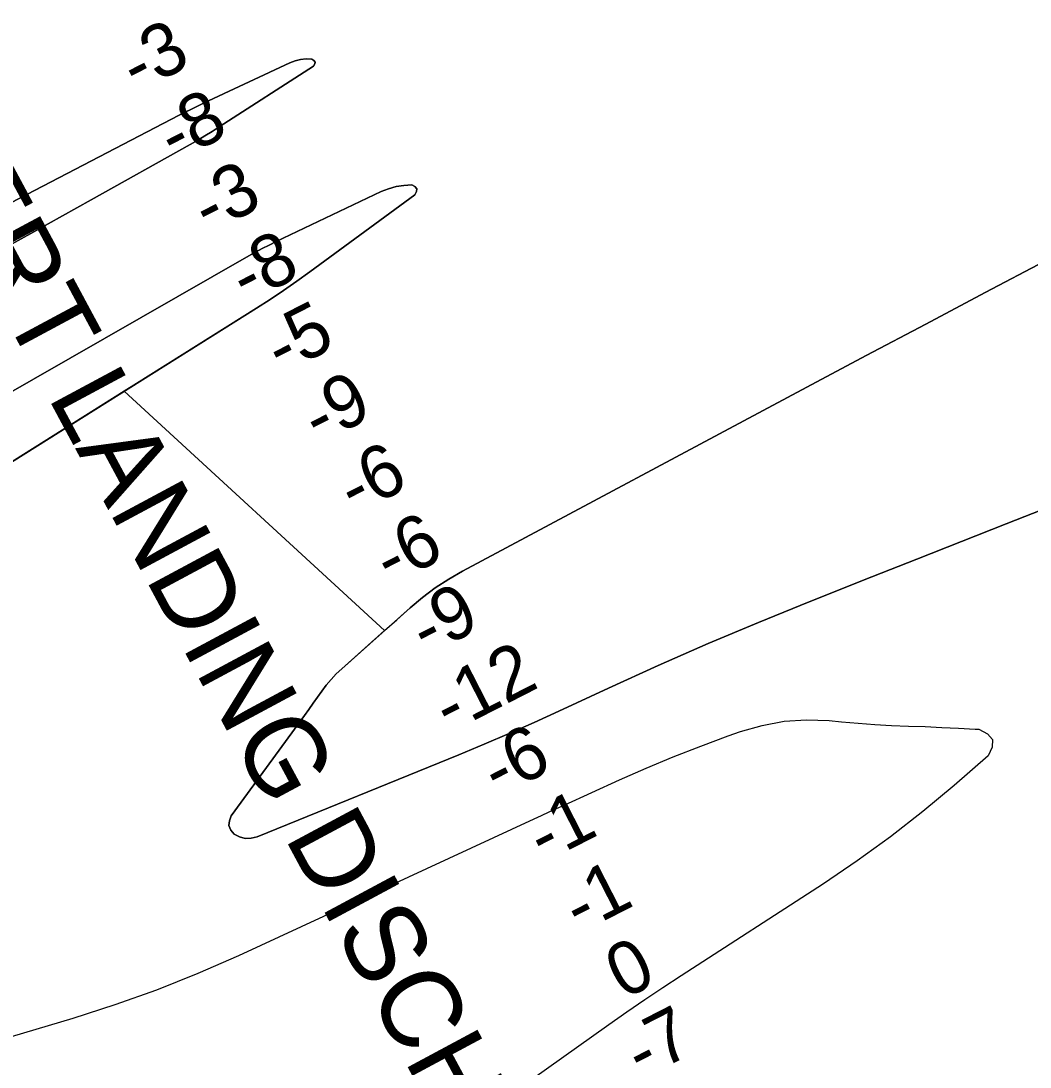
# Model space of a CAD drawing. Extents: x 3177385 to 3215275, y 903885 to 929304.
# Drawn here: x 3189350 to 3190624, y 911280 to 912601 of the extents above; entities that cross this region are included whole.
import ezdxf

# ---------------------------------------------------------------- set-up
doc = ezdxf.new("R2010")
doc.units = 0
for name, color, linetype in [('V-RIVR-RANG', 7, 'Continuous'), ('V-TOPO-DPTH', 7, 'Continuous'), ('V-TOPO-GNAM-IDEN', 7, 'Continuous'), ('V-TOPO-MINR', 7, 'Continuous')]:
    doc.layers.add(name, color=color, linetype=linetype)

msp = doc.modelspace()

# ---------------------------------------------------------------- linework, layer by layer
at = {"layer": 'V-TOPO-DPTH'}
for points in [[(3189564.8, 912490), (3189572.5, 912493.8), (3189580.2, 912497.4), (3189689.2, 912548.4), (3189695.8, 912550.8), (3189702.6, 912552.6), (3189709.6, 912553.3), (3189716.8, 912553.2), (3189719.6, 912551.5), (3189721.2, 912549.4), (3189720.7, 912546.9), (3189719, 912544.1), (3189600.1, 912467.4), (3189591.1, 912461.7), (3189582, 912456.2), (3189572.8, 912450.7), (3189563.5, 912445.4), (3189438.2, 912375.2), (3189366.1, 912335.1), (3189293.8, 912295.3), (3189221.3, 912255.9), (3189148.7, 912216.7), (3188785.3, 912022.1)], [(3189293.8, 912295.3), (3189366.1, 912335.1), (3189438.2, 912375.2), (3189563.5, 912445.4), (3189572.8, 912450.7), (3189582, 912456.2), (3189591.1, 912461.7), (3189600.1, 912467.4), (3189719, 912544.1), (3189720.7, 912546.9), (3189721.2, 912549.4), (3189719.6, 912551.5), (3189716.8, 912553.2), (3189709.6, 912553.3), (3189702.6, 912552.6), (3189695.8, 912550.8), (3189689.2, 912548.4), (3189580.2, 912497.4), (3189572.5, 912493.8), (3189564.8, 912490)], [(3188651.4, 912291.8), (3188630.9, 912279.2), (3188740.2, 912059.2), (3188762.3, 912070.9), (3188789, 912085.2), (3188875.6, 912131), (3188962.3, 912176.5), (3189549.5, 912482.3), (3189557.1, 912486.2), (3189564.8, 912490)], [(3189564.8, 912490), (3189557.1, 912486.2), (3189549.5, 912482.3), (3188962.3, 912176.5)], [(3188785.3, 912022.1), (3188851.8, 911840.7), (3188860.3, 911846.5), (3188952, 911906.5), (3189045.3, 911963.9), (3189139.7, 912019.7), (3189637.3, 912304.4), (3189645.8, 912309.1), (3189654.4, 912313.8), (3189663.2, 912318.2), (3189671.9, 912322.5), (3189804.6, 912385.7), (3189813.9, 912389.4), (3189823.3, 912392.1), (3189833, 912393.6), (3189843, 912394.1), (3189847, 912392), (3189849.4, 912389.3), (3189849, 912385.8), (3189846.9, 912381.8), (3189714.5, 912284.4), (3189698, 912272.5), (3189681.2, 912260.9)], [(3189681.2, 912260.9), (3189698, 912272.5), (3189714.5, 912284.4), (3189846.9, 912381.8), (3189849, 912385.8), (3189849.4, 912389.3), (3189847, 912392), (3189843, 912394.1), (3189833, 912393.6), (3189823.3, 912392.1), (3189813.9, 912389.4), (3189804.6, 912385.7), (3189671.9, 912322.5), (3189663.2, 912318.2), (3189654.4, 912313.8), (3189645.8, 912309.1), (3189637.3, 912304.4), (3189139.7, 912019.7)], [(3189495.5, 912143.3), (3189480.2, 912133.7), (3189808.7, 911831.2), (3189824.2, 911845), (3189841.2, 911860.1), (3189856.7, 911873), (3189872.8, 911885.1), (3189889.7, 911896.1), (3189907.2, 911906.2), (3190341.7, 912138.5), (3190416.8, 912178.5), (3190491.9, 912218.4), (3190567.1, 912258.2), (3190642.4, 912297.8)], [(3190642.4, 912297.8), (3190567.1, 912258.2), (3190491.9, 912218.4), (3190416.8, 912178.5), (3190341.7, 912138.5), (3189907.2, 911906.2), (3189889.7, 911896.1), (3189872.8, 911885.1), (3189856.7, 911873), (3189841.2, 911860.1), (3189754.6, 911782.9), (3189747.8, 911776.4), (3189741.3, 911769.6), (3189735.2, 911762.4), (3189729.6, 911754.8), (3189724.1, 911747.1), (3189718.6, 911739.4), (3189713.1, 911731.7), (3189707.5, 911724.1), (3189615.2, 911597.3), (3189612.8, 911590.9), (3189612.2, 911584.9), (3189614.6, 911579.3), (3189618.9, 911574.1), (3189625.8, 911570.6), (3189632.9, 911568.6), (3189640.3, 911568.8), (3189647.9, 911570.6), (3189902.5, 911674.4), (3189934.4, 911687.6), (3189966, 911701.2), (3189997.5, 911715.2), (3190028.9, 911729.5), (3190091.4, 911758.6), (3190154.2, 911787.1), (3190217.3, 911814.9), (3190280.8, 911841.5), (3190344.7, 911867.5), (3190424, 911898.9), (3190480.6, 911921.3), (3190537.1, 911943.7), (3190593.7, 911966.1), (3190650.2, 911988.5)], [(3189060.7, 911870.1), (3189647.1, 912238.5), (3189664.2, 912249.6), (3189681.2, 912260.9)], [(3189681.2, 912260.9), (3189664.2, 912249.6), (3189647.1, 912238.5), (3189495.5, 912143.3)], [(3189808.7, 911831.2), (3189480.2, 912133.7), (3189060.7, 911870.1)], [(3190650.2, 911988.5), (3190593.7, 911966.1), (3190537.1, 911943.7), (3190480.6, 911921.3), (3190424, 911898.9), (3190344.7, 911867.5), (3190280.8, 911841.5), (3190217.3, 911814.9), (3190154.2, 911787.1), (3190091.4, 911758.6), (3190028.9, 911729.5), (3189997.5, 911715.2), (3189966, 911701.2), (3189934.4, 911687.6), (3189902.5, 911674.4), (3189647.9, 911570.6), (3189640.3, 911568.8), (3189632.9, 911568.6), (3189625.8, 911570.6), (3189618.9, 911574.1), (3189614.6, 911579.3), (3189612.2, 911584.9), (3189612.8, 911590.9), (3189615.2, 911597.3), (3189707.5, 911724.1), (3189713.1, 911731.7), (3189718.6, 911739.4), (3189724.1, 911747.1), (3189729.6, 911754.8), (3189735.2, 911762.4), (3189741.3, 911769.6), (3189747.8, 911776.4), (3189754.6, 911782.9), (3189808.7, 911831.2)]]:
    msp.add_lwpolyline(points, dxfattribs=at)
at = {"layer": 'V-TOPO-MINR'}
for points in [[(3189293.8, 912295.3), (3189366.1, 912335.1), (3189438.2, 912375.2), (3189563.5, 912445.4), (3189572.8, 912450.7), (3189582, 912456.2), (3189591.1, 912461.7), (3189600.1, 912467.4), (3189719, 912544.1), (3189720.7, 912546.9), (3189721.2, 912549.4), (3189719.6, 912551.5), (3189716.8, 912553.2), (3189709.6, 912553.3), (3189702.6, 912552.6), (3189695.8, 912550.8), (3189689.2, 912548.4), (3189580.2, 912497.4), (3189572.5, 912493.8), (3189564.8, 912490)], [(3189564.8, 912490), (3189557.1, 912486.2), (3189549.5, 912482.3), (3188962.3, 912176.5)], [(3189681.2, 912260.9), (3189698, 912272.5), (3189714.5, 912284.4), (3189846.9, 912381.8), (3189849, 912385.8), (3189849.4, 912389.3), (3189847, 912392), (3189843, 912394.1), (3189833, 912393.6), (3189823.3, 912392.1), (3189813.9, 912389.4), (3189804.6, 912385.7), (3189671.9, 912322.5), (3189663.2, 912318.2), (3189654.4, 912313.8), (3189645.8, 912309.1), (3189637.3, 912304.4), (3189139.7, 912019.7)], [(3190642.4, 912297.8), (3190567.1, 912258.2), (3190491.9, 912218.4), (3190416.8, 912178.5), (3190341.7, 912138.5), (3189907.2, 911906.2), (3189889.7, 911896.1), (3189872.8, 911885.1), (3189856.7, 911873), (3189841.2, 911860.1), (3189754.6, 911782.9), (3189747.8, 911776.4), (3189741.3, 911769.6), (3189735.2, 911762.4), (3189729.6, 911754.8), (3189724.1, 911747.1), (3189718.6, 911739.4), (3189713.1, 911731.7), (3189707.5, 911724.1), (3189615.2, 911597.3), (3189612.8, 911590.9), (3189612.2, 911584.9), (3189614.6, 911579.3), (3189618.9, 911574.1), (3189625.8, 911570.6), (3189632.9, 911568.6), (3189640.3, 911568.8), (3189647.9, 911570.6), (3189902.5, 911674.4), (3189934.4, 911687.6), (3189966, 911701.2), (3189997.5, 911715.2), (3190028.9, 911729.5), (3190091.4, 911758.6), (3190154.2, 911787.1), (3190217.3, 911814.9), (3190280.8, 911841.5), (3190344.7, 911867.5), (3190424, 911898.9), (3190480.6, 911921.3), (3190537.1, 911943.7), (3190593.7, 911966.1), (3190650.2, 911988.5)], [(3189060.7, 911870.1), (3189647.1, 912238.5), (3189664.2, 912249.6), (3189681.2, 912260.9)], [(3189337.8, 911318.5), (3189415.4, 911341.7), (3189468.7, 911358.9), (3189521.4, 911377.6), (3189573.4, 911398.5), (3189624.7, 911420.9), (3189997.5, 911593.4), (3190006.9, 911597.7), (3190016.4, 911602.1), (3190025.8, 911606.4), (3190035.3, 911610.7), (3190105.2, 911642.5), (3190139.2, 911657.4), (3190173.3, 911671.8), (3190207.9, 911685.3), (3190242.7, 911698.2), (3190258, 911703.7), (3190285.5, 911711.5), (3190313.4, 911716.8), (3190341.6, 911718.4), (3190370.2, 911717.5), (3190385.8, 911716), (3190406.8, 911714.2), (3190427.9, 911712.6), (3190448.9, 911711.4), (3190470, 911710.6), (3190491.1, 911709.9), (3190512.2, 911709), (3190533.3, 911708), (3190554.4, 911706.8), (3190559.2, 911706.5), (3190570, 911700.8), (3190576.3, 911693.5), (3190575.7, 911683.9), (3190570.7, 911672.8), (3190527.9, 911635.7), (3190488.2, 911602.6), (3190447.5, 911570.6), (3190405.5, 911540.4), (3190362.7, 911511.4), (3190183, 911395.1), (3190160.1, 911380), (3190137.2, 911364.7), (3190114.6, 911349.1), (3190092, 911333.3), (3189801.9, 911126.9)]]:
    msp.add_lwpolyline(points, dxfattribs=at)

# ---------------------------------------------------------------- texts
at = {"layer": 'V-RIVR-RANG'}
for s, p in [('-3', (3189495.7, 912510.3)), ('-8', (3189543.4, 912422.4)), ('-3', (3189586.3, 912332)), ('-8', (3189634, 912244.1)), ('-5', (3189678.4, 912154.5)), ('-9', (3189725.4, 912066.2)), ('-6', (3189770.5, 911976.9)), ('-6', (3189815.8, 911887.8)), ('-9', (3189861.4, 911798.8)), ('-12', (3189890.5, 911701.4)), ('-6', (3189951.8, 911620.4)), ('-1', (3190009.6, 911537.6)), ('-1', (3190054.9, 911448.5)), ('0', (3190110.6, 911364.7)), ('-7', (3190133.1, 911263.9))]:
    msp.add_text(s, height=67, rotation=27.0992, dxfattribs=at).set_placement(p)
at = {"layer": 'V-TOPO-GNAM-IDEN'}
msp.add_text('TARBERT LANDING DISCHARGE RANGE', height=100, rotation=298.2461, dxfattribs=at).set_placement((3189069.7, 912709.7))

doc.saveas('drawing.dxf')
